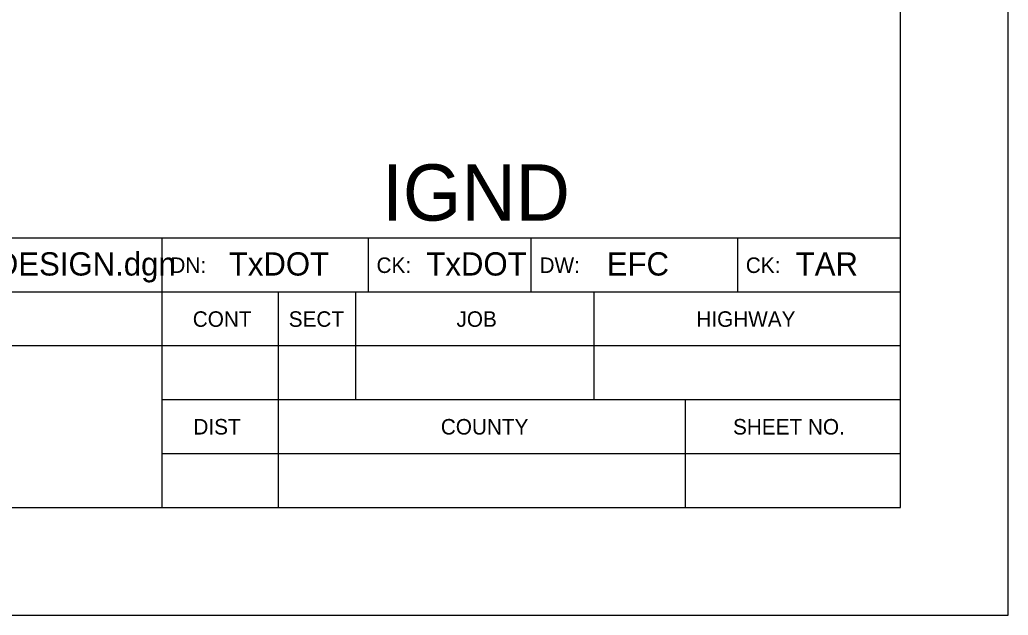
# Model space of a CAD drawing. Extents: x 998.6 to 1033.3, y 1000 to 1011.
# Drawn here: x 1014.706 to 1017, y 1000 to 1001.382 of the extents above; entities that cross this region are included whole.
import ezdxf

# ---------------------------------------------------------------- set-up
doc = ezdxf.new("R2010")
doc.units = 0
for name, color, linetype in [('D_BATCH_PLOT', 7, 'Continuous'), ('D_SHEET', 7, 'Continuous'), ('Working Level 1', 7, 'Continuous')]:
    doc.layers.add(name, color=color, linetype=linetype)

msp = doc.modelspace()

# ---------------------------------------------------------------- linework, layer by layer
at = {"layer": 'D_BATCH_PLOT'}
msp.add_lwpolyline([(1000, 1000), (1017, 1000), (1017, 1011), (1000, 1011)], close=True, dxfattribs=at)
at = {"layer": 'D_SHEET'}
for p, q in [((1017, 1000), (1017, 1011)), ((1016.75, 1000.25), (1016.75, 1010.75)), ((1016.75, 1000.875), (1013.725, 1000.875)), ((1015.0363, 1000.25), (1015.0363, 1000.875)), ((1015.5152, 1000.75), (1015.5152, 1000.875)), ((1015.8931, 1000.75), (1015.8931, 1000.875)), ((1016.3721, 1000.75), (1016.3721, 1000.875)), ((1016.75, 1000.75), (1013.725, 1000.75)), ((1015.3063, 1000.25), (1015.3063, 1000.75)), ((1015.4863, 1000.5), (1015.4863, 1000.75)), ((1016.039, 1000.5), (1016.039, 1000.75)), ((1016.75, 1000.625), (1013.725, 1000.625)), ((1016.75, 1000.5), (1015.0363, 1000.5)), ((1016.251, 1000.25), (1016.251, 1000.5)), ((1016.75, 1000.375), (1015.0363, 1000.375)), ((1001, 1000.25), (1016.75, 1000.25)), ((1000, 1000), (1017, 1000))]:
    msp.add_line(p, q, dxfattribs=at)

# ---------------------------------------------------------------- texts
for s, height, p in [('19PDENG014-BEAM DESIGN.dgn', 0.053999, (1013.9442, 1000.7885)), (' TxDOT ', 0.054, (1015.1712, 1000.7885)), ('TxDOT', 0.054, (1015.6497, 1000.7885)), ('  EFC  ', 0.054, (1016.0281, 1000.7885)), ('TAR  ', 0.054, (1016.5068, 1000.7885)), ('CONT', 0.036, (1015.1075, 1000.6695)), ('SECT', 0.036, (1015.3302, 1000.6695)), ('JOB', 0.036, (1015.7195, 1000.6695)), ('HIGHWAY', 0.036, (1016.2762, 1000.6695)), ('DIST', 0.036, (1015.109, 1000.4195)), ('COUNTY', 0.036, (1015.6832, 1000.4195)), ('SHEET NO.', 0.036, (1016.3613, 1000.4195))]:
    msp.add_text(s, height=height, dxfattribs=at).set_placement(p)
for s, p in [('DN:', (1015.0555, 1000.7945)), ('CK:', (1015.534, 1000.7945)), ('DW:', (1015.9123, 1000.7945)), ('CK:', (1016.391, 1000.7945))]:
    msp.add_text(s, height=0.036, rotation=360, dxfattribs=at).set_placement(p)
at = {"layer": 'Working Level 1'}
msp.add_text('IGND', height=0.1305, dxfattribs=at).set_placement((1015.5466, 1000.9161))

doc.saveas('drawing.dxf')
